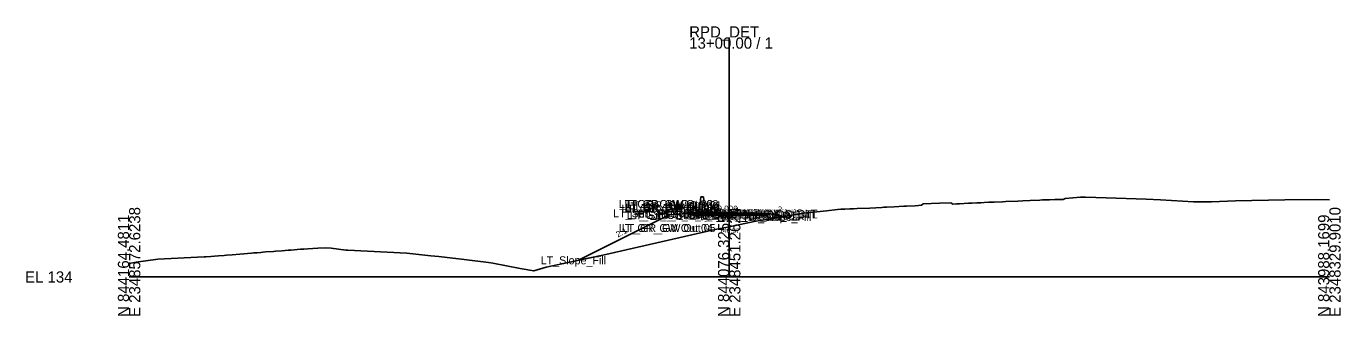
# Model space of a CAD drawing. Extents: x -26 to 2348503, y -10 to 844218.
# Drawn here: x -25.7 to 302.8, y 2990.3 to 3062.7 of the extents above; entities that cross this region are included whole.
import ezdxf

# ---------------------------------------------------------------- set-up
doc = ezdxf.new("R2010")
doc.units = 0
for name, color, linetype in [('Default', 7, 'Continuous'), ('Exist Cross Section Cell', 7, 'Continuous'), ('Exist XS Center Line Elevation Label', 7, 'Continuous'), ('Exist XS Ground Line', 7, 'Continuous'), ('Old_Level_1', 7, 'Continuous'), ('Prop CMT Pvmt Course 1', 7, 'Continuous'), ('Prop CMT Pvmt Course 2', 7, 'Continuous'), ('Prop CMT Pvmt Course 3', 7, 'Continuous'), ('Prop CMT Pvmt Surface', 7, 'Continuous'), ('Prop CMT Pvmt Surface Shoulder', 7, 'Continuous'), ('Prop CMT Shld Paved Course 1', 7, 'Continuous'), ('Prop CMT Shld Paved Course 2', 7, 'Continuous'), ('Prop CMT Shld Paved Course 3', 7, 'Continuous'), ('Prop CMT Slope Grass', 7, 'Continuous'), ('Prop CMT Subgrade Earthwork', 7, 'Continuous'), ('Prop XS Earthwork Shape', 7, 'Continuous'), ('Prop XS SE Text', 7, 'Continuous'), ('Typical Median Barrier CELL', 7, 'Continuous')]:
    doc.layers.add(name, color=color, linetype=linetype)

# ---------------------------------------------------------------- blocks, each defined once
blk = doc.blocks.new('TYPE T DOUBLE FACE BARRIER')
at = {"layer": 'Typical Median Barrier CELL'}
for p, q in [((-0.33, 3.83), (-0.6, 1.3)), ((0, 3.83), (-0.33, 3.83)), ((0, 3.83), (0.33, 3.83)), ((0.33, 3.83), (0.6, 1.3)), ((-0.75, 0.91), (-1.21, 0.25)), ((-1.21, -0.17), (-1.21, 0.25)), ((0, 0), (0, 0)), ((0.75, 0.91), (1.21, 0.25)), ((1.21, -0.17), (1.21, 0.25)), ((-1.21, -0.17), (1.21, -0.17))]:
    blk.add_line(p, q, dxfattribs=at)
for centre, start, end in [((-1.43, 1.38), 325.0039, 353.9447), ((1.43, 1.38), 186.0553, 214.9937)]:
    blk.add_arc(centre, 0.833, start, end, dxfattribs=at)

msp = doc.modelspace()

# ---------------------------------------------------------------- linework, layer by layer
at = {"layer": 'Exist Cross Section Cell'}
for p, q in [((150, 3000), (150, 3059.89)), ((0, 3000), (150, 3000)), ((150, 3000), (300, 3000))]:
    msp.add_line(p, q, dxfattribs=at)
at = {"layer": 'Exist XS Ground Line'}
msp.add_lwpolyline([(0, 3003.38), (1.81, 3003.7), (7.16, 3004.41), (18.73, 3005.01), (19.24, 3005.04), (20.43, 3005.13), (21.36, 3005.21), (22.33, 3005.32), (23.8, 3005.41), (24.35, 3005.45), (25.76, 3005.56), (27.72, 3005.73), (30.56, 3005.96), (31.16, 3006.01), (31.98, 3006.07), (32.95, 3006.15), (33.47, 3006.2), (34.13, 3006.27), (36.11, 3006.39), (36.69, 3006.44), (38.26, 3006.57), (39.8, 3006.69), (40.44, 3006.74), (42.87, 3006.92), (43.64, 3006.97), (44.67, 3007.05), (45.96, 3007.15), (47.19, 3007.23), (49.1, 3007.26), (50.55, 3007.22), (54.2, 3006.71), (54.68, 3006.68), (69.44, 3005.96), (75.43, 3005.29), (77.44, 3005.08), (83.75, 3004.38), (89.8, 3003.61), (90.91, 3003.47), (97.71, 3002.12), (101.16, 3001.5), (104.27, 3002.48), (118.39, 3005.43), (146.51, 3011.87), (150, 3012.57), (151.6, 3012.89), (156.25, 3013.85), (158.85, 3014.3), (168.66, 3015.93), (174.35, 3016.55), (177.09, 3016.87), (177.92, 3016.92), (178.89, 3016.96), (180.18, 3017.02), (180.5, 3017.04), (181.08, 3017.06), (182.02, 3017.1), (185.11, 3017.22), (188.16, 3017.4), (188.67, 3017.43), (189.39, 3017.46), (191.23, 3017.55), (193.63, 3017.67), (194.31, 3017.7), (196.45, 3017.81), (197.35, 3017.86), (198.09, 3017.97), (198.47, 3018.3), (202.53, 3018.46), (205.4, 3018.57), (205.87, 3018.24), (206.81, 3018.28), (207.55, 3018.32), (209.77, 3018.42), (210.13, 3018.44), (210.63, 3018.46), (211.92, 3018.53), (212.86, 3018.58), (213.7, 3018.62), (214.88, 3018.67), (215.51, 3018.7), (216.22, 3018.73), (218.32, 3018.82), (219.11, 3018.86), (222.11, 3018.99), (223.36, 3019.05), (225.25, 3019.13), (227.61, 3019.23), (228.32, 3019.25), (230.08, 3019.32), (231.35, 3019.37), (231.84, 3019.39), (233.49, 3019.38), (233.95, 3019.64), (237.81, 3019.92), (239.09, 3019.96), (244.2, 3019.78), (254.2, 3019.44), (257.82, 3019.28), (266.07, 3018.79), (268.84, 3018.77), (270.56, 3018.81), (276.55, 3019), (288.85, 3019.28), (296.64, 3019.35), (300, 3019.29)], dxfattribs=at)
at = {"layer": 'Prop CMT Pvmt Course 1'}
for p, q in [((150, 3016.01), (142, 3016.06)), ((142, 3016.06), (142, 3015.81)), ((150, 3015.76), (150, 3016.01)), ((150, 3016.01), (158, 3015.96)), ((150, 3015.76), (150, 3016.01)), ((158, 3015.96), (158, 3015.71)), ((142, 3015.81), (150, 3015.76)), ((150, 3015.76), (150, 3015.88)), ((150, 3015.88), (150, 3015.88)), ((150, 3015.88), (150, 3015.76)), ((150, 3015.76), (150, 3015.88)), ((150, 3015.88), (150, 3015.88)), ((150, 3015.88), (150, 3015.76)), ((150, 3015.76), (150, 3015.76)), ((158, 3015.71), (150, 3015.76)), ((150, 3015.76), (150, 3015.76))]:
    msp.add_line(p, q, dxfattribs=at)
at = {"layer": 'Prop CMT Pvmt Course 2'}
for p, q in [((142, 3015.81), (150, 3015.76)), ((150, 3015.76), (142, 3015.81)), ((142, 3015.81), (142, 3015.81)), ((150, 3015.76), (150, 3015.76)), ((158, 3015.71), (150, 3015.76)), ((150, 3015.76), (150, 3015.76)), ((150, 3015.76), (158, 3015.71)), ((158, 3015.71), (158, 3015.71))]:
    msp.add_line(p, q, dxfattribs=at)
at = {"layer": 'Prop CMT Pvmt Course 3'}
for p, q in [((150, 3015.76), (142, 3015.81)), ((142, 3015.81), (142, 3015.47)), ((142, 3015.47), (150, 3015.42)), ((150, 3015.42), (150, 3015.76)), ((150, 3015.76), (158, 3015.71)), ((150, 3015.42), (150, 3015.76)), ((158, 3015.37), (150, 3015.42)), ((158, 3015.71), (158, 3015.37))]:
    msp.add_line(p, q, dxfattribs=at)
at = {"layer": 'Prop CMT Pvmt Surface'}
for q in [(142, 3016.06), (158, 3015.96)]:
    msp.add_line((150, 3016.01), q, dxfattribs=at)
at = {"layer": 'Prop CMT Pvmt Surface Shoulder'}
for p, q in [((142, 3016.06), (142, 3016.06)), ((158, 3015.96), (158, 3015.96))]:
    msp.add_line(p, q, dxfattribs=at)
at = {"layer": 'Prop CMT Shld Paved Course 1'}
for p, q in [((142, 3016.06), (141.74, 3015.8)), ((142, 3016.06), (142, 3016.06)), ((142, 3015.81), (142, 3016.06)), ((158, 3015.96), (158, 3015.96)), ((158, 3015.96), (158.26, 3015.7)), ((158, 3015.71), (158, 3015.96)), ((141.74, 3015.8), (142, 3015.81)), ((158.26, 3015.7), (158, 3015.71))]:
    msp.add_line(p, q, dxfattribs=at)
at = {"layer": 'Prop CMT Shld Paved Course 2'}
for p, q in [((142, 3015.81), (141.74, 3015.8)), ((141.74, 3015.8), (142, 3015.81)), ((141.74, 3015.8), (141.74, 3015.8)), ((142, 3015.81), (142, 3015.81)), ((158, 3015.71), (158.26, 3015.7)), ((158.26, 3015.7), (158, 3015.71)), ((158, 3015.71), (158, 3015.71)), ((158.26, 3015.7), (158.26, 3015.7))]:
    msp.add_line(p, q, dxfattribs=at)
at = {"layer": 'Prop CMT Shld Paved Course 3'}
for p, q in [((141.24, 3015.79), (140.9, 3015.45)), ((140.9, 3015.45), (142, 3015.47)), ((141.74, 3015.8), (141.24, 3015.79)), ((142, 3015.81), (141.74, 3015.8)), ((142, 3015.47), (142, 3015.81)), ((158, 3015.71), (158.26, 3015.7)), ((158, 3015.37), (158, 3015.71)), ((159.1, 3015.35), (158, 3015.37)), ((158.26, 3015.7), (158.76, 3015.69)), ((158.76, 3015.69), (159.1, 3015.35))]:
    msp.add_line(p, q, dxfattribs=at)
at = {"layer": 'Prop CMT Slope Grass'}
for p, q in [((142, 3016.06), (135, 3015.5)), ((158, 3015.96), (162, 3015.64)), ((135, 3015.5), (112.35, 3004.17)), ((162, 3015.64), (163.22, 3015.03))]:
    msp.add_line(p, q, dxfattribs=at)
at = {"layer": 'Prop CMT Subgrade Earthwork'}
for p, q in [((140.9, 3015.45), (140.43, 3015.93)), ((142, 3015.47), (140.9, 3015.45)), ((150, 3015.42), (142, 3015.47)), ((150, 3015.42), (158, 3015.37)), ((158, 3015.37), (159.1, 3015.35)), ((159.1, 3015.35), (159.57, 3015.83))]:
    msp.add_line(p, q, dxfattribs=at)
at = {"layer": 'Prop XS Earthwork Shape'}
msp.add_lwpolyline([(140.9, 3015.45), (140.43, 3015.93), (135, 3015.5), (112.35, 3004.17), (118.39, 3005.43), (146.51, 3011.87), (150, 3012.57), (151.6, 3012.89), (156.25, 3013.85), (158.85, 3014.3), (163.22, 3015.03), (162, 3015.64), (159.57, 3015.83), (159.1, 3015.35), (158, 3015.37), (150, 3015.42), (142, 3015.47)], close=True, dxfattribs=at)

# ---------------------------------------------------------------- block references
at = {"layer": 'Old_Level_1', "yscale": -0.9999999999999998, "rotation": 179.5598762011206}
msp.add_blockref('TYPE T DOUBLE FACE BARRIER', (143.21, 3016.21), dxfattribs=at)

# ---------------------------------------------------------------- texts
at = {"layer": 'Default'}
for s, height, p in [('LT_GR_GW Out 03', 2, (122.44, 3017.24)), ('LT_GR_GW Out 02', 2, (123.78, 3017.24)), ('LT_Sub_Trench_Out_DLT', 2, (120.99, 3014.93)), ('LT_GR_GW Out 06', 2, (123.06, 3016.07)), ('LT_GR_GW Out 09', 2, (123.78, 3016.65)), ('LT_GR_GW Out 07', 2, (123.78, 3016.07)), ('LT_GR_GW Out 08', 2, (124.05, 3016.36)), ('LT_GS_OS_CTL', 2, (124.37, 3014.5)), ('LT_GR_GW Out 01', 2, (124.61, 3016.94)), ('LT_Sub_Trench_Out', 2, (125.11, 3014.45)), ('LT_PS3_Shelf_Out', 2, (127.23, 3014.79)), ('LT_PS3_OEOP', 2, (131.98, 3014.8)), ('LT_PS2_OEOP', 2, (131.98, 3014.8)), ('LT_Sub_OEOT', 2, (132.08, 3014.47)), ('LT_PV3_OEOT', 2, (132.17, 3014.81)), ('LT_PV2_OEOT', 2, (132.17, 3014.81)), ('LT_PV1_OEOT', 2, (132.74, 3015.06)), ('LT_PS1_OEOP', 2, (132.8, 3015.06)), ('RT_Sub_OEEOP', 2, (139.17, 3014.42)), ('LT_Sub_OEEOP', 2, (139.21, 3014.42)), ('RT_PV2_OEEOP', 2, (139.26, 3014.76)), ('RT_PV3_OEEOP', 2, (139.26, 3014.76)), ('LT_PV2_OEEOP', 2, (139.31, 3014.76)), ('LT_PV3_OEEOP', 2, (139.31, 3014.76)), ('RT_PV1_OEEOP', 2, (139.83, 3014.88)), ('LT_PV1_OEEOP', 2, (139.87, 3014.88)), ('RT_PV2_IEEOP', 2, (139.91, 3014.76)), ('LT_PV2_IEEOP', 2, (139.95, 3014.76)), ('RT_Sub_Trench_Out_DLT', 2, (140.09, 3014.83)), ('RT_PV1_IEEOP', 2, (140.47, 3014.88)), ('LT_PV1_IEEOP', 2, (140.52, 3014.88)), ('RT_Sub_Trench_Out', 2, (143.25, 3014.35)), ('PV2_PGL', 2, (143.91, 3014.76)), ('PV1_PGL', 2, (144.47, 3015.01)), ('RT_PS3_Shelf_Out', 2, (144.69, 3014.69)), ('RT_Sub_OEOT', 2, (148.03, 3014.37)), ('RT_PV3_OEOT', 2, (148.13, 3014.71)), ('RT_PV2_OEOT', 2, (148.13, 3014.71)), ('RT_PS3_OEOP', 2, (148.44, 3014.7)), ('RT_PS2_OEOP', 2, (148.44, 3014.7)), ('RT_PV1_OEOT', 2, (148.69, 3014.96)), ('RT_PS1_OEOP', 2, (148.76, 3014.96)), ('RT_GS_OS_CTL', 2, (151.32, 3014.64)), ('RT_Slope_Fill', 2, (153.7, 3014.03)), ('LT_GR_GW Out 04', 2, (122.44, 3011.24)), ('LT_GR_GW Out 05', 2, (123.11, 3011.24)), ('LT_Slope_Fill', 2, (102.87, 3003.17)), ('-', 0.0001, (0, 3000))]:
    msp.add_text(s, height=height, dxfattribs=at).set_placement(p)
at = {"layer": 'Exist Cross Section Cell'}
for s, p in [('RPD_DET', (140, 3059.89)), ('13+00.00 / 1', (140, 3057.09)), ('EL 134', (-26, 2998.6))]:
    msp.add_text(s, height=2.8, dxfattribs=at).set_placement(p)
for s, p in [('E 2348572.6238', (2.8, 2990)), ('E 2348451.2624', (152.8, 2990)), ('E 2348329.9010', (302.8, 2990)), ('N 844164.4811', (0, 2990)), ('N 844076.3255', (150, 2990)), ('N 843988.1699', (300, 2990))]:
    msp.add_text(s, height=2.8, rotation=90, dxfattribs=at).set_placement(p)
at = {"layer": 'Exist XS Center Line Elevation Label'}
msp.add_text('146.57', height=1.2, dxfattribs=at).set_placement((147.52, 3010.97))
at = {"layer": 'Prop XS SE Text'}
for s, rotation, p in [('0.006', 359.6511, (147.06, 3016.36)), ('2:1', 333.4349, (161.7, 3016.49)), ('2:1', 26.5651, (122.17, 3009.84))]:
    msp.add_text(s, height=1.5, rotation=rotation, dxfattribs=at).set_placement(p)

doc.saveas('drawing.dxf')
